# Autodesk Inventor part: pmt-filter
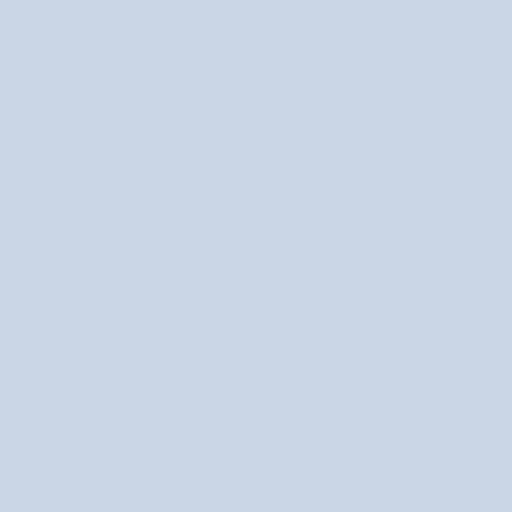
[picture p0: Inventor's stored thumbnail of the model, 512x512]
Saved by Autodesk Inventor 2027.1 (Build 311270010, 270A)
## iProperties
Created: 2026-08
Part Number: pmt-filter
Material: Generic
Document SubType Name: Modeling
Designer: dunge
Density: 1 g/cm^3
Appearance: Default
Author: dunge
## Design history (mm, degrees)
sketch "Sketch1"
  geometry: C1 r 17.78 at (0, 0); 1 further point
  constraints: 1 centre point, 1 coincident
  dimensions: "d0" = 35.56 diameter of C1
extrude "Extrusion1" new body sketch "Sketch1" stored distance "d1" = 0.635; taper "d2" = 0 deg
body "Solid1"
node "Finishes"
node "Finish1" dims "Finish1_Area" = 205.72324
